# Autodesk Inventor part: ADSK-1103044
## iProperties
Shininess: 41.0
Length Units: 11272
Angle Units: 11279
Time Units: 11290
Mass Units: 11286
Length Display Precision: 4
Angle Display Precision: 2
Compacted: True
Created: 2000-07
Part Number: ADSK-1103044
Document SubType Name: Modeling
Description: ENGINE HEAD
Mass: 37.1194 g
Surface Area: 215.954 cm^2
Volume: 13.6972 cm^3
Density: 2.71 g/cm^3
Material: Aluminum-6061
Density: 0.0
Volumn: 0.0
Area: 0.0
PropertySet Name: Model Information
Control State: 0
Master: False
Checked Out: False
Author: Autodesk, Inc.
